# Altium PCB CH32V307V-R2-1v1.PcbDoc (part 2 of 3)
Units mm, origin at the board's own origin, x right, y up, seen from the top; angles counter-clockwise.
Board outline 80 x 115 mm, 2 copper layers (Top Layer, Bottom Layer); 122 components, 134 nets, 559 pads, 721 vias.
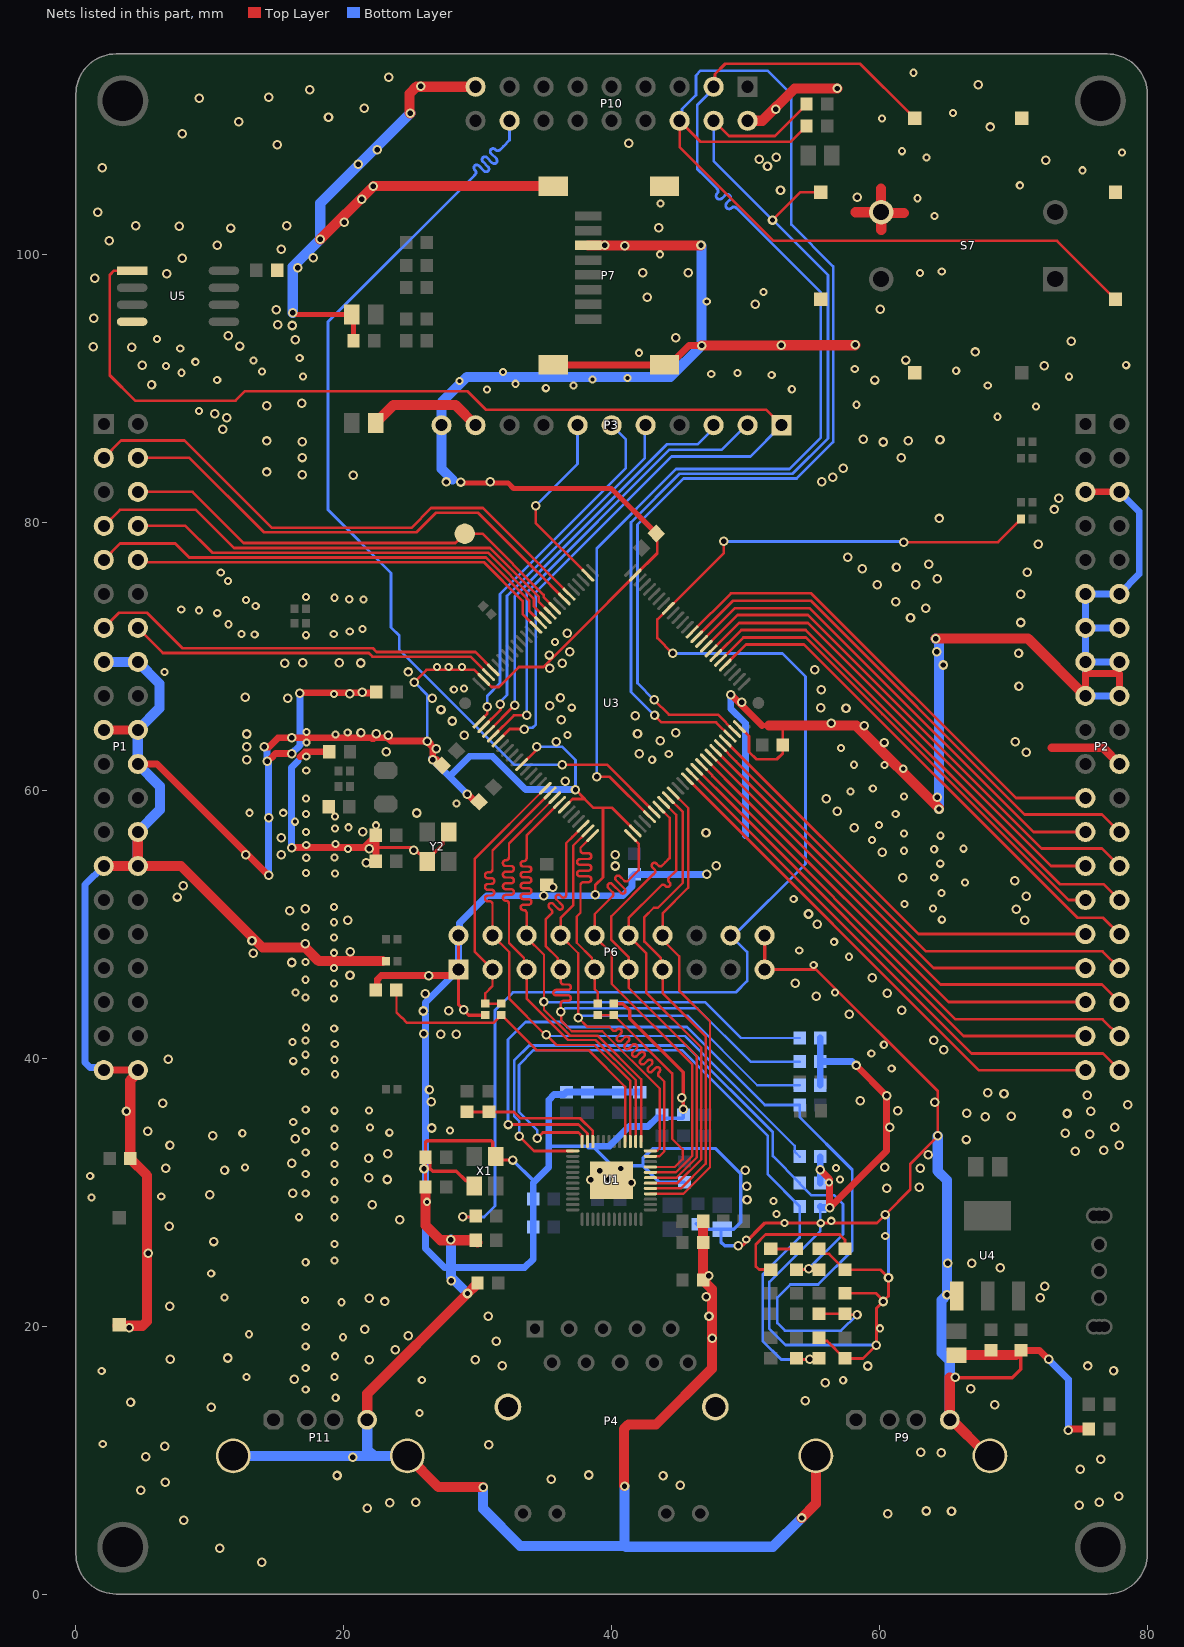
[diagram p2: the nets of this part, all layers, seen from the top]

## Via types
v1: diameter 0.711, hole 0.406, Top Layer to Bottom Layer, tented both sides, 507 vias
v2: diameter 0.61, hole 0.305, Top Layer to Bottom Layer, tented both sides, 214 vias

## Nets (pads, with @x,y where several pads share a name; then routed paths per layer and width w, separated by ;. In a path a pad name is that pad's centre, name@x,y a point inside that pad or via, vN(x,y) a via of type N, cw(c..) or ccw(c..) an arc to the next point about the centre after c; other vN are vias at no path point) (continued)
DVP_PCLK: P10.16 U3.31 | length 75.2
  Top Layer w0.203: v1(36.309,61.928) 39.654,61.928 U3.31@43.182,58.4
  Bottom Layer w0.203: P10.16@32.38,110.007 32.38,108.56 31.917,108.098 31.651,107.831 cw(c31.498,107.984) 31.345,107.831 31.304,107.872 ccw(c31.152,107.72) 30.999,107.567 31.391,107.175 cw(c31.238,107.023) 31.085,106.87 30.694,107.262 ccw(c30.541,107.109) 30.388,106.956 30.78,106.565 cw(c30.627,106.412) 30.475,106.259 30.083,106.651 ccw(c29.93,106.498) 29.778,106.346 29.819,106.305 cw(c29.666,106.152) 29.819,105.999 29.747,105.927 18.818,94.998 18.818,80.963 23.533,76.248 23.533,72.169 24.147,71.555 24.147,70.505 32.724,61.928 v1(36.309,61.928)
DVP_VSYNC: P10.3 S3.1 U3.30 | length 92.6
  Top Layer w0.203: v1(38.89,61.016) 39.859,61.016 U3.30@42.828,58.047 ; P10.3@47.62,112.547 47.721,112.649 47.721,113.501 48.484,114.264 58.545,114.264 62.228,110.581 S3.1@62.626,110.182
  Bottom Layer w0.203: v1(38.89,61.016) 38.89,78.079 44.815,84.005 53.284,84.005 55.622,86.343 55.622,97.192 49.386,103.428 49.314,103.5 ccw(c49.134,103.32) 48.955,103.5 ; P10.3@47.62,112.547 47.62,112.397 46.391,111.168 46.391,106.423 47.004,105.81 47.877,104.937 cw(c47.697,104.757) 47.877,104.578 ; 47.876,104.577 ccw(c48.056,104.397) 47.876,104.218 ccw(c48.056,104.397) 48.235,104.218 48.452,104.435 cw(c48.632,104.255) 48.812,104.435 cw(c48.632,104.255) 48.812,104.075 48.595,103.858 ccw(c48.774,103.679) 48.954,103.499
FSMC_A16: P2.27 U3.58 | length 36.3
  Top Layer w0.203: U3.58@47.425,70.421 49.512,72.509 54.668,72.509 72.816,54.36 P2.27@75.379,54.36
FSMC_A17: P2.28 U3.59 | length 39.6
  Top Layer w0.203: U3.59@47.071,70.775 49.406,73.11 54.666,73.11 72.1,55.676 76.603,55.676 P2.28@77.919,54.36
FSMC_A18: P2.25 U3.60 | length 36.6
  Top Layer w0.203: U3.60@46.718,71.128 49.202,73.613 54.785,73.613 71.497,56.9 P2.25@75.379,56.9
FSMC_CLK: P1.6 tp1.1 U3.84 | length 35.4
  Top Layer w0.203: P1.6@4.621,82.3 8.706,82.3 12.524,78.482 28.34,78.482 tp1.1@29.031,79.174 30.348,79.174 34.924,74.597 34.924,74.436 U3.84@35.757,73.603
FSMC_D0: P2.26 U3.61 | length 39.8
  Top Layer w0.203: U3.61@46.364,71.482 49.051,74.168 54.873,74.168 70.841,58.2 76.619,58.2 P2.26@77.919,56.9
FSMC_D1: P2.23 U3.62 | length 36.9
  Top Layer w0.203: U3.62@46.01,71.835 48.899,74.724 54.909,74.724 70.193,59.44 P2.23@75.379,59.44
FSMC_D2: P1.3 U3.81 | length 41.2
  Top Layer w0.203: P1.3@2.081,84.84 3.37,86.129 8.114,86.129 14.633,79.61 25.046,79.61 26.528,81.092 30.39,81.092 U3.81@36.818,74.664
FSMC_D3: P1.4 U3.82 | length 37.4
  Top Layer w0.203: P1.4@4.621,84.84 8.471,84.84 14.032,79.28 25.432,79.28 26.888,80.736 30.029,80.736 34.412,76.353 34.422,76.353 U3.82@36.464,74.31
FSMC_D4: P2.39 U3.38 | length 38.7
  Top Layer w0.203: U3.38@45.657,60.875 67.412,39.12 P2.39@75.379,39.12
FSMC_D5: P2.40 U3.39 | length 41.1
  Top Layer w0.203: U3.39@46.01,61.229 66.885,40.354 76.685,40.354 P2.40@77.919,39.12
FSMC_D6: P2.37 U3.40 | length 37.3
  Top Layer w0.203: U3.40@46.364,61.582 49.049,58.897 66.286,41.66 P2.37@75.379,41.66
FSMC_D7: P2.38 U3.41 | length 39.6
  Top Layer w0.203: U3.41@46.718,61.936 47.519,61.134 47.519,61.079 65.689,42.909 76.67,42.909 P2.38@77.919,41.66
FSMC_D8: P2.35 U3.42 | length 35.8
  Top Layer w0.203: U3.42@47.071,62.289 49.752,59.608 65.16,44.2 P2.35@75.379,44.2
FSMC_D9: P2.36 U3.43 | length 38.1
  Top Layer w0.203: U3.43@47.425,62.643 64.559,45.509 76.611,45.509 P2.36@77.919,44.2
FSMC_D10: P2.33 U3.44 | length 34.3
  Top Layer w0.203: U3.44@47.778,62.996 64.034,46.74 P2.33@75.379,46.74
FSMC_D11: P2.34 U3.45 | length 36.7
  Top Layer w0.203: U3.45@48.132,63.35 49.303,62.179 63.489,47.993 76.666,47.993 P2.34@77.919,46.74
FSMC_D12: P2.31 U3.46 | length 32.9
  Top Layer w0.203: U3.46@48.485,63.704 62.908,49.28 P2.31@75.379,49.28
FSMC_D13: P2.32 U3.55 | length 39
  Top Layer w0.203: U3.55@48.485,69.36 50.029,70.905 54.365,70.905 74.773,50.496 76.703,50.496 P2.32@77.919,49.28
FSMC_D14: P2.29 U3.56 | length 36.1
  Top Layer w0.203: U3.56@48.132,69.714 49.838,71.42 54.513,71.42 60.215,65.717 74.112,51.82 P2.29@75.379,51.82
FSMC_D15: P2.30 U3.57 | length 39.3
  Top Layer w0.203: U3.57@47.778,70.068 49.688,71.977 54.491,71.977 73.465,53.003 76.737,53.003 P2.30@77.919,51.82
FSMC_NBL0: P1.13 U3.97 | length 31.3
  Top Layer w0.203: P1.13@2.081,72.14 3.21,73.269 5.298,73.269 7.941,70.626 22.167,70.626 22.451,70.342 29.83,70.342 31.161,69.011 U3.97@31.161,69.007
FSMC_NBL1: P1.14 U3.98 | length 27.6
  Top Layer w0.203: P1.14@4.621,72.14 6.495,70.267 21.867,70.267 22.141,69.992 29.469,69.992 U3.98@30.808,68.653
FSMC_NE1_NCE2: P1.10 U3.88 | length 32.4
  Top Layer w0.203: P1.10@4.621,77.22 4.797,77.044 30.466,77.044 33.356,74.154 33.356,73.176 U3.88@34.343,72.189
FSMC_NOE: P1.7 U3.85 | length 37.2
  Top Layer w0.203: P1.7@2.081,79.76 3.279,80.958 8.956,80.958 11.802,78.111 30.907,78.111 34.569,74.45 34.569,74.085 U3.85@35.404,73.25
FSMC_NWAIT: P1.9 U3.87 | length 36
  Top Layer w0.203: P1.9@2.081,77.22 3.307,78.446 7.419,78.446 8.465,77.4 30.613,77.4 33.858,74.155 33.858,73.382 U3.87@34.697,72.542
FSMC_NWE: P1.8 U3.86 | length 33.6
  Top Layer w0.203: P1.8@4.621,79.76 8.173,79.76 10.178,77.755 30.76,77.755 34.213,74.302 34.213,73.733 34.404,73.543 U3.86@35.05,72.896
GND: C1.1 C2.1 C3.1 C4.1 C5.1 C6.1 C7.1 C8.1 C9.1 C10.2 C11.1 C12.1 C13.1 C14.1 C15.1 C16.1 C17.1 C18.2 C19.2 C20.1 C21.1 C22.1 C23.1 C24.1 C25.2 C26.1 C27.1 C28.1 C29.2 C30.1 C31.2 C32.1 C33.2 C34.1 C35.1 C36.1 C37.1 C38.1 C39.2 C40.2 C41.2 P1.15 P1.16 P1.19 P1.20 P1.22 P1.26 P1.27 P1.28 P1.39 P1.40 P2.5 P2.6 P2.11 P2.12 P2.13 P2.14 P2.15 P2.16 P2.17 P2.18 P2.22 P3.11 P4.0 P6.1 P6.2 P6.19 P6.20 P7.6 P7.10 P9.0 P9.4 P10.2 P10.17 P11.0 P11.4 pad.2 R2.2 R4.2 R7.2 R9.2 R15.2 R22.2 R23.2 R26.2 R38.2 R43.2 R47.2 R54.1 R58.1 S1.1 S3.2 S4.2 S5.2 S6.2 S7.3 U1.0 U3.10 U3.19 U3.27 U3.49 U3.74 U3.99 U4.1 U5.4 X1.2 X1.4 Y2.2 Y2.4 | length 909.4
  Top Layer w0.203: v1(25.277,68.097) 26.187,69.007 29.747,69.007 U3.99@30.454,68.3 30.461,68.3 31.028,67.733 31.583,67.733 33.071,69.22 34.909,69.22 37.663,71.973 U3.74@41.768,76.078 43.406,77.717 43.406,78.604 43.351,78.66 43.351,79.062 C26.1@43.406,79.118 ; U3.10@33.282,61.936 33.289,61.936 34.427,63.073 v1(34.427,63.273) ; U3.19@36.464,58.754 37.082,59.372 37.985,59.372 ; v1(37.302,60.068) 37.985,59.385 37.985,59.372 ; v1(38.771,52.202) 38.771,52.922 39.35,53.501 39.35,58.705 ; U3.27@41.768,56.986 40.049,58.705 39.35,58.705 ; U3.49@49.546,64.764 50.253,64.057 50.253,62.884 50.804,62.333 52.334,62.333 52.784,62.783 C37.1@52.784,63.403 52.784,64.634 ; 51.225,64.845 51.743,64.845 ; P6.19@51.43,46.634 55.267,46.634 64.359,37.542 v1(64.359,34.207) ; C18.2@55.495,25.765 55.859,25.402 56.225,25.402 57.402,24.225 R23.2@57.427,24.225 57.428,24.224 60.058,24.224 v1(60.676,23.606) 60.676,22.243 v1@60.319,21.886 ; C29.2@55.859,18.917 55.884,18.892 56.099,18.892 56.71,18.281 ; 56.286,18.705 57.402,17.589 R47.2@57.427,17.589 58.773,17.589 v1(59.772,18.588) 59.772,21.339 v1@60.319,21.886 ; v2@56.511,27.704 59.809,27.704 v1(60.442,28.337) 62.301,30.196 62.301,32.108 v1@64.379,34.187 ; C25.2@57.427,22.461 59.744,22.461 v1@60.319,21.886 ; v1(60.276,21.844) v1@60.319,21.886 ; 37.985,59.372 38.651,58.705 39.35,58.705
  Top Layer w0.254: 22.397,55.777 22.43,55.743 25.186,55.743 25.654,55.276 25.779,55.276 Y2.2@26.227,54.828 ; C13.1@26.103,30.404 C14.1@26.103,32.525 ; Y2.2@26.227,54.703 Y2.2@26.227,54.828 ; Y2.4@27.672,56.731 27.379,56.438 27.379,55.98 Y2.2@26.227,54.828 ; P6.2@28.57,49.174 P6.1@28.57,46.634 28.57,43.997 29.336,43.231 C32.1@30.564,43.231 ; X1.2@29.649,30.339 29.649,30.439 29.226,30.862 29.126,30.862 28.41,31.578 26.632,31.578 26.441,31.769 26.441,32.251 26.166,32.525 C14.1@26.103,32.525 ; X1.4@31.484,32.383 31.507,32.407 v1(32.627,32.407) ; X1.4@31.599,32.689 31.127,33.162 31.127,33.724 31.015,33.835 26.214,33.835 26.103,33.724 C14.1@26.103,32.614 C14.1@26.103,32.525 ; C34.1@40.165,44.081 40.84,44.081 41.346,43.574 41.346,42.966 45.336,38.976 v1(45.336,36.208) ; 49.83,26.083 51.451,27.704 v2@56.511,27.704 ; P6.19@51.43,46.634 P6.20@51.43,49.174 ; 65.253,16.152 69.917,16.152 70.563,16.798 C40.2@70.563,18.194
  Top Layer w0.381: v1(16.193,95.67) 16.193,95.537 C35.1@20.602,95.537 20.722,95.417 C36.1@20.722,93.583 ; v1@28.737,82.957 32.275,82.957 32.676,82.556 39.983,82.556 43.128,79.41 43.241,79.41 C26.1@43.315,79.485
  Top Layer w0.508: P1.39@2.081,39.12 P1.40@4.621,39.12 ; P1.22@4.621,61.98 6.066,61.98 v1(14.388,53.659) ; v1(14.076,63.256) 14.401,63.256 15.078,63.933 22.058,63.933 22.103,63.889 22.241,63.889 22.285,63.933 23.281,63.933 23.529,63.685 v1(26.237,63.685) ; 14.604,62.442 14.913,62.751 v1(16.101,62.751) ; v1(16.102,55.734) 21.501,55.734 C15.1@22.397,56.63 ; v1(16.723,67.272) 16.751,67.3 21.355,67.3 v1(21.383,67.327) ; 16.733,62.512 17.11,62.889 C11.1@18.928,62.889 C11.1@18.908,62.869 ; v1@21.383,67.272 22.34,67.272 C19.2@22.416,67.348 ; R38.2@22.397,45.098 22.503,45.205 22.503,45.893 22.801,46.191 28.108,46.191 P6.1@28.264,46.347 ; C16.1@22.397,54.719 22.397,55.777 C15.1@22.397,56.63 ; C15.1@22.397,56.655 C15.1@22.397,56.63 ; v1@26.44,63.561 26.385,63.506 26.385,63.467 26.649,63.203 v1(26.649,62.305) 26.936,62.305 27.334,61.907 C30.1@27.334,61.876 ; v1(29.23,59.712) 29.285,59.712 29.84,59.157 C31.2@30.101,59.157 ; P7.10@35.65,91.776 P7.10@43.95,91.776 44.325,91.776 45.775,93.226 v1(46.721,93.226) ; v1(48.895,67.132) 48.938,67.132 51.225,64.845 ; v1(55.584,31.669) 56.276,30.977 v1(56.276,28.828) 60.533,33.085 v1(60.533,37.198) 58.283,39.447 v1(58.283,39.466) ; C40.2@70.563,18.194 71.947,18.194 v1(72.626,17.515) ; v1(74.107,12.216) 74.162,12.216 74.275,12.329 R58.1@75.638,12.329 ; P2.17@75.379,67.06 75.379,68.732 77.919,68.732 P2.18@77.919,67.06 ; P2.5@75.379,82.3 P2.6@77.919,82.3
  Top Layer w0.66: P1.19@2.081,64.52 P1.20@4.621,64.52 ; 72.897,63.192 76.708,63.192 P2.22@77.919,61.98
  Top Layer w0.762: P1.27@2.081,54.36 P1.28@4.621,54.36 ; S1.1@3.124,20.032 4.974,20.032 5.308,20.367 5.308,31.26 C17.1@4.055,32.513 4.055,38.355 4.621,38.921 P1.40@4.621,39.12 ; P1.26@4.621,56.9 P1.28@4.621,54.36 ; v1(18.252,101.161) v1(22.217,105.126) P7.10@35.65,105.126 ; P11.4@21.747,13.012 21.747,14.948 v1(29.24,22.441) 29.902,23.103 29.902,23.128 C10.2@29.986,23.212 ; R54.1@22.902,47.26 18.144,47.26 17.124,48.279 13.934,48.279 7.852,54.36 P1.28@4.621,54.36 ; P11.0@24.747,10.312 27.078,7.982 v1(30.404,7.982) ; v1(24.967,110.572) 24.918,110.621 24.918,112.043 25.423,112.547 P10.17@29.84,112.547 ; C13.1@26.103,30.404 26.103,27.542 27.228,26.416 R2.2@29.849,26.416 29.849,26.391 R2.2@29.986,26.254 ; P7.6@38.25,100.701 v1(39.504,100.701) v1(46.675,100.701) ; v1(40.965,8.059) 40.919,8.105 40.919,12.319 41.254,12.654 43.315,12.654 47.487,16.827 47.487,22.776 46.832,23.43 R15.2@46.832,23.455 C21.1@46.832,26.241 C7.1@46.832,27.833 ; P7.10@43.95,105.126 P7.10@44.325,105.126 ; v1(46.721,93.226) 52.636,93.226 v1(52.655,93.244) 58.166,93.244 v1(58.189,93.267) ; P10.2@50.16,110.007 51.256,110.007 53.666,112.418 v1(56.851,112.418) ; 51.743,64.845 58.27,64.845 64.447,58.668 v1(64.447,58.616) ; v1(54.191,5.679) 55.253,6.741 P9.0@55.253,10.312 ; 58.216,103.173 60.117,103.173 S7.3@60.126,103.183 ; 60.124,104.944 60.124,103.185 S7.3@60.126,103.183 ; 60.129,101.862 S7.3@60.129,103.18 ; 61.836,103.114 60.195,103.114 S7.3@60.129,103.18 ; v1(64.204,71.341) 71.098,71.341 P2.17@75.379,67.06 ; 65.253,16.152 P9.4@65.253,13.012 65.403,13.012 67.883,10.533 P9.0@67.883,10.357 ; C39.2@65.749,17.839 C40.2@70.183,17.839 ; S7.3@60.126,103.183 S7.3@60.129,103.18
  Bottom Layer w0.203: v1(25.277,68.097) 26.237,67.138 v1(26.237,63.685) ; v1(34.427,63.273) 36.305,63.273 37.302,62.275 v1(37.302,60.068) ; R22.2@55.584,28.93 55.584,27.105 51.777,23.297 51.777,19.8 52.989,18.588 v1(59.772,18.588) ; v1(60.442,28.337) 60.676,28.104 v1@60.676,23.708
  Bottom Layer w0.254: v1(32.627,32.407) 34.156,30.878 34.156,30.721 34.152,30.716 ; 35.31,33.443 38.318,33.443 ; 38.583,33.443 40.039,31.987 42.343,31.987 ; C8.1@43.722,35.52 45.306,35.52 45.336,35.55 v1(45.336,36.208) ; C6.1@45.433,30.757 43.573,30.757 42.343,31.987 ; C4.1@46.322,27.653 46.722,27.252 C5.1@48.17,27.252 ; v1(49.467,25.996) 48.446,25.996 48.17,26.272 C5.1@48.17,27.252 ; 42.343,31.987 42.343,32.53 43.078,33.265 47.772,33.265 49.64,31.397 49.64,27.769 49.123,27.252 C5.1@48.17,27.252
  Bottom Layer w0.508: P1.39@2.081,39.12 1.891,39.31 1.061,39.31 0.687,39.685 0.687,52.966 P1.27@2.081,54.36 ; v1(14.076,63.256) 14.279,63.054 v1(14.279,62.169) 14.388,62.06 v1(14.388,53.659) ; v1(16.101,62.751) 16.723,63.373 v1(16.723,67.272) ; v1(16.102,55.734) 16.102,61.714 16.579,62.191 ; v1@26.032,43.535 25.977,43.48 25.977,43.442 26.097,43.322 26.097,42.005 26.027,41.934 26.027,41.896 26.082,41.841 26.027,41.786 26.027,41.747 26.097,41.676 26.097,31.929 26.031,31.862 26.031,31.823 26.086,31.768 26.031,31.713 26.031,31.674 26.097,31.607 26.097,25.802 27.518,24.381 28.004,24.381 33.509,24.381 34.152,25.023 C23.1@34.152,27.397 C1.1@34.152,29.489 34.152,30.716 35.31,31.875 35.31,33.443 35.31,36.891 35.71,37.29 36.441,37.29 C24.1@36.628,37.478 C22.1@38.206,37.478 C28.1@40.521,37.478 C27.1@42.03,37.478 ; v1@26.097,43.535 26.097,44.162 28.074,46.138 P6.1@28.57,46.634 P6.2@28.57,49.174 28.652,49.256 28.652,50.11 30.675,52.133 v1(34.933,52.133) 40.824,52.133 41.527,52.836 41.527,53.542 C38.1@41.718,53.732 v1(47.112,53.732) ; v1@26.544,62.398 27.887,61.055 ; v1(29.23,59.712) 27.887,61.055 ; v1(37.302,60.068) 33.585,60.068 31.103,62.55 29.383,62.55 27.887,61.055 ; 38.318,33.443 38.583,33.443 39.859,33.443 41.315,34.899 42.714,34.899 43.378,35.563 C8.1@43.722,35.563 ; C3.1@38.953,30.987 pad.2@39.782,30.987 40.387,30.987 C2.1@40.387,31.006 ; v1(48.895,67.132) 48.895,66.133 50.006,65.022 50.006,56.626 ; R22.2@55.584,28.93 55.648,28.867 56.237,28.867 v1(56.276,28.828) ; R26.2@55.584,30.681 v1(55.584,31.669) R43.2@55.584,32.656 ; R9.2@55.584,37.992 R7.2@55.584,39.753 ; R4.2@55.584,41.515 R7.2@55.584,39.753 ; 57.941,39.753 R7.2@55.584,39.753 ; v1(72.626,17.515) 74.107,16.034 v1(74.107,12.216) ; P2.18@77.919,67.06 P2.17@75.379,67.06 P2.15@75.379,69.6 ; P2.16@77.919,69.6 P2.15@75.379,69.6 ; P2.14@77.919,72.14 P2.13@75.379,72.14 ; P2.6@77.919,82.3 79.392,80.827 79.392,76.154 P2.12@77.919,74.68 P2.11@75.379,74.68 P2.13@75.379,72.14 ; P2.15@75.379,69.6 P2.13@75.379,72.14
  Bottom Layer w0.762: P1.15@2.081,69.6 P1.16@4.621,69.6 6.234,67.987 6.234,66.134 P1.20@4.621,64.52 P1.22@4.621,61.98 6.274,60.328 6.274,58.553 P1.26@4.621,56.9 P1.28@4.621,54.36 ; P11.0@11.747,10.312 22.23,10.312 ; v1(16.193,95.67) 16.193,99.102 v1(18.252,101.161) 18.252,103.857 v1(24.967,110.572) ; P11.4@21.747,13.012 21.747,10.795 22.23,10.312 ; P11.0@24.747,10.312 22.23,10.312 ; v1(28.004,26.462) 28.004,24.381 28.004,23.677 v1(29.24,22.441) ; 28.109,83.219 27.3,84.029 P3.11@27.3,87.274 27.3,88.977 29.208,90.885 44.381,90.885 v1(46.721,93.226) 46.721,100.655 v1(46.675,100.701) ; v1(30.404,7.982) 30.404,6.356 33.172,3.589 40.907,3.589 40.965,3.647 v1(40.965,8.059) ; 41.083,3.529 52.041,3.529 v1(54.191,5.679) ; v1(64.204,71.341) 64.447,71.099 v1(64.447,58.616) ; v1(64.359,34.207) 64.359,31.577 65.045,30.892 v1(65.045,22.351) 64.642,21.948 64.642,18.024 65.253,17.413 P9.4@65.253,13.012
  other v1: 13.885,2.377 10.725,3.431 8.059,5.507 60.629,5.991 65.38,6.174 63.49,6.201 21.743,6.417 74.918,6.639 23.435,6.832 25.38,6.838 76.426,6.847 77.881,7.315 4.841,7.747 45.128,8.126 6.672,8.357 35.505,8.576 43.839,8.831 19.497,8.85 38.301,8.889 74.997,9.33 76.53,10.07 20.682,10.222 5.204,10.238 64.619,10.558 63.096,10.584 6.646,11.047 30.825,11.158 10.118,13.934 68.602,14.134 4.078,14.318 54.446,14.418 66.825,15.336 55.95,15.768 16.301,16.044 65.674,16.173 77.478,16.686 31.847,17.039 59.141,17.026 75.551,17.029 21.906,17.506 29.812,17.506 7.047,17.544 11.325,17.625 23.855,18.241 31.373,18.891 47.516,19.107 24.811,19.271 21.58,19.755 3.972,19.876 30.787,20.729 47.273,20.754 6.998,21.489 23.046,21.845 21.904,22.072 72.004,22.137 47.057,22.211 72.331,22.995 28.032,23.39 47.246,23.75 69.007,24.367 65.102,24.713 66.891,24.713 5.412,25.455 10.306,26.322 6.972,27.473 24.166,27.962 22.128,29.079 50.11,29.443 10.01,29.8 16.197,29.916 60.545,30.285 62.957,30.38 50.076,30.448 41.454,30.709 23.246,30.953 38.43,30.939 21.867,31.096 39.129,31.612 49.974,31.642 11.097,31.655 25.992,31.768 40.695,31.773 6.703,31.781 63.055,31.793 60.387,31.872 16.129,32.169 21.849,32.541 63.647,32.811 23.279,32.892 74.628,33.06 76.743,33.144 77.916,33.502 7.025,33.509 66.468,33.938 16.394,33.996 10.207,34.219 75.701,34.317 73.871,34.412 5.356,34.568 26.565,34.798 60.783,34.846 77.558,34.871 67.908,35.646 69.832,35.676 74.006,35.881 66.518,35.913 3.777,36.054 75.766,36.044 61.378,36.076 78.535,36.532 6.499,36.639 64.139,36.72 26.533,36.77 58.57,36.826 45.248,37.046 75.521,37.251 69.299,37.363 68.086,37.422 26.401,37.657 6.909,39.935 64.797,40.636 64.05,41.348 28.397,41.799 27.234,41.813 25.988,41.841 57.728,43.281 25.939,43.535 27.848,43.569 61.662,43.578 28.953,43.614 55.291,44.629 26.092,44.814 60.594,44.848 53.721,45.608 59.453,46.027 26.358,46.151 20.467,46.188 16.106,47.156 13.241,47.845 20.492,47.956 17.137,48.55 13.148,48.79 55.347,50.022 20.286,50.305 70.856,50.322 54.702,50.777 15.974,51.017 70.225,51.117 17.137,51.182 7.568,52.045 70.965,52.109 35.607,52.759 8.025,52.879 70.098,53.264 61.735,53.495 40.266,54.362 47.8,54.385 21.675,54.592 12.668,55.204 15.345,55.216 40.275,55.2 60.194,55.374 25.243,55.528 21.89,55.644 15.328,56.48 47.049,56.832 21.405,56.924 58.125,57.21 14.395,57.975 25.458,58.319 56.859,58.456 56.035,59.384 64.326,59.491 36.541,60.699 12.773,62.286 42.057,62.73 70.96,62.865 23.164,62.904 26.894,63.13 12.773,63.252 60.35,63.581 35.869,63.641 70.129,63.639 43.626,63.718 16.128,63.923 29.007,64.124 23.329,64.135 12.773,64.217 22.413,64.226 41.933,64.25 21.286,64.301 44.8,64.299 58.88,64.818 56.406,65.028 28.109,65.188 36.229,65.286 41.781,65.586 27.262,66.046 57.503,66.148 55.613,66.171 35.37,66.324 49.727,66.602 15.83,66.895 26.609,66.902 12.643,66.952 36.183,66.93 20.463,67.226 55.66,67.525 70.418,67.8 24.804,68.849 55.168,69.006 35.383,69.124 64.778,69.371 15.605,69.512 21.263,69.519 36.323,69.517 16.945,69.533 19.679,69.546 35.336,70.116 70.384,70.24 36.884,70.351 64.266,70.351 36.688,71.74 70.556,72.543 62.319,72.882 63.441,73.605 61.222,74.079 70.556,74.639 59.826,75.35 62.718,75.375 64.313,75.824 71.037,76.289 58.705,76.546 61.272,76.671 63.665,76.895 57.633,77.419 71.854,78.397 64.463,80.31 73.037,80.983 73.386,81.806 27.641,83.037 28.737,83.033 30.949,83.056 55.682,83.04 56.511,83.392 16.902,83.56 20.721,83.541 14.261,83.782 57.29,84.07 61.621,84.847 16.902,84.862 60.283,86.021 16.902,86.032 14.247,86.097 62.152,86.117 64.521,86.194 58.786,86.224 10.948,86.965 11.247,87.845 10.381,88.133 14.247,88.737 16.872,88.906 5.647,90.302 59.664,90.65 4.939,91.736 72.318,91.731 61.973,92.143 67.148,92.743 4.181,93.096 1.281,93.134 12.232,93.188 74.332,93.543 16.395,93.67 44.795,93.791 11.373,93.956 16.149,94.721 15.076,94.765 1.324,95.259 14.971,95.912 60.071,95.921 50.724,96.305 42.661,96.817 1.423,98.239 6.797,98.578 42.342,98.645 45.722,98.645 16.578,99.02 7.929,99.735 17.726,99.788 15.328,100.42 40.992,100.678 10.538,100.719 2.491,101.039 11.547,101.999 43.51,102.018 7.732,102.122 4.459,102.171 15.754,102.164 20.028,102.42 1.619,103.185 21.331,104.146 58.333,104.306 52.611,104.822 1.979,106.494 51.641,106.6 21.066,106.771 72.406,107.056 51.022,107.138 52.298,107.298 22.512,107.859 15.046,108.231 41.266,108.321 7.93,109.04 68.259,109.544 12.164,109.923 18.861,110.275 52.245,110.857 21.546,110.946 9.194,111.702 14.397,111.765 17.468,112.323 25.733,112.587 67.37,112.684 23.369,113.273
  other v2: 2.006,11.207 25.666,13.526 19.396,14.658 17.159,15.281 25.829,15.972 57.293,15.96 19.304,16.196 12.732,16.215 1.924,16.647 17.159,16.888 19.346,17.749 17.159,18.495 19.936,19.171 12.933,19.396 60.04,19.841 17.161,19.951 19.82,21.785 17.109,21.95 11.087,22.132 10.101,23.923 17.159,24.771 19.304,24.916 19.304,26.141 50.054,26.481 60.433,26.73 55.616,27.69 52.907,27.713 56.4,27.869 16.651,28.138 19.304,28.134 52.323,28.364 26.218,29.288 52.092,29.342 19.304,29.46 1.169,29.614 6.372,29.682 17.159,29.897 56.229,30.726 19.304,30.786 57.042,30.956 1.067,31.213 17.159,31.352 56.763,31.81 12.63,31.859 19.304,32.113 17.159,32.959 19.304,33.439 12.426,34.409 23.402,34.448 17.159,34.566 27.931,34.603 19.304,34.766 21.97,34.835 16.231,35.234 19.304,36.092 21.892,36.113 17.159,36.173 19.342,38.809 17.124,39.018 60.915,39.249 16.23,39.787 19.3,39.897 17.152,40.274 59.393,40.371 60.327,41.014 19.328,41.069 16.182,41.225 17.152,41.334 19.286,42.227 17.18,42.282 19.269,44.459 17.137,44.549 16.395,44.922 56.687,44.908 19.269,45.599 17.137,45.866 19.269,46.739 55.089,46.963 17.137,47.182 57.716,47.586 19.269,47.879 54.012,48.059 56.62,48.701 19.269,49.019 17.137,49.815 19.269,50.159 64.657,50.354 63.998,51.195 19.269,51.299 61.868,51.528 53.596,51.895 64.627,52.356 66.394,53.126 64.087,53.503 19.335,53.792 17.189,53.839 64.539,54.535 17.201,54.976 19.316,54.988 61.824,55.5 20.309,55.62 64.087,55.611 66.283,55.655 17.201,55.936 19.373,56.014 59.446,56.301 64.568,56.625 61.841,56.788 17.176,56.909 19.354,57.172 20.359,57.25 22.397,57.399 59.975,57.42 16.349,57.67 19.354,58.065 17.189,58.235 61.212,58.244 12.958,58.332 15.482,58.332 28.41,59.027 17.189,59.397 61.824,59.56 57.826,59.923 59.504,60.158 17.201,61.494 61.779,61.623 60.388,61.895 58.091,61.925 43.03,62.297 17.201,62.542 44.264,62.721 57.12,63.161 17.214,63.578 36.7,64.135 19.378,64.18 20.295,64.331 17.214,64.374 37.024,66.183 19.282,67.211 28.217,67.552 28.974,67.606 6.622,68.843 26.957,69.214 27.836,69.224 28.832,69.23 35.781,71.077 17.188,71.595 13.349,71.642 12.372,71.679 19.254,71.686 20.449,71.862 21.394,72.047 11.396,72.412 10.551,73.238 9.199,73.454 7.864,73.526 13.424,73.782 12.692,74.223 21.468,74.252 20.412,74.28 19.319,74.391 17.188,74.446 11.349,75.65 10.814,76.289 68.816,87.908 9.189,88.334 71.679,88.671 58.282,88.801 30.693,89.934 53.457,89.958 35.088,90.04 37.161,90.243 68.085,90.23 32.813,90.365 28.651,90.58 10.55,90.648 38.583,90.69 41.184,90.812 74.161,90.898 16.946,90.92 51.954,91.015 47.443,91.096 49.394,91.178 7.896,91.193 31.892,91.251 13.884,91.295 65.731,91.344 58.153,91.471 6.739,91.703 78.423,91.757 8.916,92.009 13.272,92.111 16.708,92.281 42.038,92.681 7.793,92.996 6.058,93.711 47.106,96.505 51.352,97.221 63.018,98.632 64.655,98.758 43.619,100.037 64.116,102.898 43.663,103.837 62.843,104.222 70.482,105.189 75.167,106.31 63.505,107.277 78.12,107.634 61.672,107.735 60.195,110.18 65.491,110.587 62.538,113.592
GPHY_RGMII_MCO: P6.18 R14.2 R48.2 U3.67 | length 108.2
  Top Layer w0.203: v1(28.886,28.16) 29.79,28.16 R14.2@29.849,28.219 ; v1(44.562,70.234) 43.415,71.381 43.415,72.775 U3.67@44.243,73.603 48.38,77.741 v1(48.38,78.599) ; v1(61.799,78.545) 68.846,78.545 70.343,80.041 70.368,80.041 70.566,80.24 R48.2@70.566,80.265
  Bottom Layer w0.203: v1(28.886,28.16) 30.481,28.16 31.289,28.968 31.289,43.59 32.628,44.929 49.271,44.929 50.125,45.782 50.125,47.94 P6.18@48.89,49.174 49.123,49.174 54.475,54.527 54.475,68.518 52.759,70.234 v1(44.562,70.234) ; v1(48.38,78.599) 61.745,78.599 v1(61.799,78.545)
GPHY_RGMII_RXC: R38.1 R49.1 U1.28 | length 25.7
  Top Layer w0.178: R38.1@23.937,45.098 23.937,43.441 23.937,43.416 24.313,43.04 24.338,43.04 24.729,42.648 31.187,42.648 31.522,42.983 31.522,43.02 31.733,43.231 31.783,43.231 31.994,43.02 31.994,43.01 34.387,40.616 38.269,40.616 41.018,37.867 41.018,33.804 U1.28@41,33.786
GPHY_RGMII_RXC_P: C32.2 P6.3 R49.2 U3.15 | length 20.3
  Top Layer w0.178: R49.2@31.758,44.081 C32.2@30.564,44.081 30.564,44.853 31.11,45.399 P6.3@31.11,46.634 29.769,47.976 29.769,54.886 U3.15@35.05,60.168
GPHY_RGMII_RXD0: P6.5 U1.26 U3.17 | length 36.8
  Top Layer w0.178: P6.5@33.365,46.349 P6.5@33.5,46.214 ; U3.17@35.757,59.461 32.335,56.039 32.335,55.363 32.335,55.01 cw(c32.119,55.01) 32.119,54.794 32.097,54.794 ccw(c32.097,54.578) 32.097,54.362 32.497,54.362 cw(c32.497,54.146) 32.497,53.93 32.097,53.93 ccw(c32.097,53.714) 32.097,53.498 32.497,53.498 cw(c32.497,53.283) 32.497,53.067 32.097,53.067 ccw(c32.097,52.851) 32.097,52.635 32.497,52.635 cw(c32.497,52.419) 32.497,52.203 32.097,52.203 ccw(c32.097,51.987) 32.097,51.771 32.119,51.771 cw(c32.119,51.555) 32.335,51.555 32.335,51.466 32.335,48.612 33.463,47.484 33.463,46.821 P6.5@33.65,46.634 33.65,44.464 36.747,41.367 38.803,41.367 41.8,38.37 U1.26@41.8,33.786
GPHY_RGMII_RXD1: P6.6 R4.1 U1.25 U3.18 | length 56.8
  Top Layer w0.178: U3.18@36.111,59.107 34.948,57.944 33.65,56.646 33.65,55.258 33.65,54.932 cw(c33.447,54.932) 33.447,54.729 33.415,54.729 ccw(c33.415,54.526) 33.415,54.323 33.808,54.323 cw(c33.808,54.119) 33.808,53.916 33.415,53.916 ccw(c33.415,53.713) 33.415,53.51 33.808,53.51 cw(c33.808,53.307) 33.808,53.103 33.415,53.103 ccw(c33.415,52.9) 33.415,52.697 33.808,52.697 cw(c33.808,52.494) 33.808,52.291 33.415,52.291 ccw(c33.415,52.087) 33.415,51.884 33.808,51.884 cw(c33.808,51.681) 33.808,51.478 33.415,51.478 ccw(c33.415,51.275) 33.415,51.071 33.447,51.071 cw(c33.447,50.868) 33.65,50.868 33.65,50.779 P6.6@33.65,49.174 33.65,49.034 34.95,47.733 v1(34.95,44.221) 34.95,43.631 36.884,41.698 38.94,41.698 42.2,38.437 U1.25@42.2,33.786
  Bottom Layer w0.178: v1(34.95,44.221) 34.995,44.177 46.999,44.177 49.661,41.515 R4.1@54.044,41.515
GPHY_RGMII_RXD2: P6.7 R7.1 U1.24 U3.23 | length 56.3
  Top Layer w0.178: U3.23@37.879,57.34 37.07,56.531 36.608,56.069 36.608,52.472 36.608,52.204 cw(c36.405,52.204) 36.262,52.06 36.159,52.163 ccw(c36.015,52.019) 35.871,52.163 ccw(c36.015,52.019) 35.871,51.876 36.297,51.45 cw(c36.154,51.306) 36.297,51.162 cw(c36.154,51.306) 36.01,51.162 35.635,51.538 ccw(c35.491,51.394) 35.347,51.538 ccw(c35.491,51.394) 35.347,51.25 35.511,51.087 cw(c35.367,50.943) 35.511,50.799 35.448,50.736 35.074,50.362 35.074,48.389 35.986,47.476 35.986,46.838 P6.7@36.19,46.634 36.209,46.615 36.209,45.806 36.209,45.717 ccw(c36.412,45.717) 36.412,45.514 36.756,45.514 cw(c36.756,45.311) 36.756,45.108 35.844,45.108 ccw(c35.844,44.905) 35.844,44.701 36.756,44.701 cw(c36.756,44.498) 36.756,44.295 36.412,44.295 ccw(c36.412,44.092) 36.209,44.092 36.209,43.479 36.209,43.477 36.228,43.458 36.228,42.82 37.02,42.028 39.303,42.028 43.594,37.737 43.594,33.274 43.415,33.094 42.908,33.094 U1.24@42.9,33.086
  Bottom Layer w0.178: v1(36.195,43.485) 36.293,43.485 36.54,43.731 46.392,43.731 50.37,39.753 R7.1@54.044,39.753
GPHY_RGMII_RXD3: P6.8 R9.1 U1.23 U3.24 | length 55.3
  Top Layer w0.178: U3.24@38.232,56.986 37.122,55.876 37.122,51.417 36.19,50.485 P6.8@36.19,49.174 37.516,47.849 v1(37.516,43.028) 38.174,42.37 39.818,42.37 40.016,42.171 40.079,42.108 ccw(c40.223,42.252) 40.366,42.108 40.406,42.148 cw(c40.55,42.005) 40.694,42.148 cw(c40.55,42.005) 40.694,41.861 40.441,41.608 ccw(c40.585,41.465) 40.441,41.321 ccw(c40.585,41.465) 40.728,41.321 40.981,41.574 cw(c41.125,41.43) 41.268,41.574 cw(c41.125,41.43) 41.268,41.286 41.016,41.034 ccw(c41.159,40.89) 41.016,40.746 ccw(c41.159,40.89) 41.303,40.746 41.556,40.999 cw(c41.699,40.855) 41.843,40.712 41.59,40.459 ccw(c41.734,40.315) 41.59,40.171 ccw(c41.734,40.315) 41.878,40.171 42.131,40.424 cw(c42.274,40.281) 42.418,40.424 cw(c42.274,40.281) 42.418,40.137 42.165,39.884 ccw(c42.309,39.74) 42.165,39.597 ccw(c42.309,39.74) 42.452,39.597 42.705,39.85 cw(c42.849,39.706) 42.993,39.85 cw(c42.849,39.706) 42.993,39.562 42.74,39.309 ccw(c42.883,39.166) 42.74,39.022 ccw(c42.883,39.166) 43.027,39.022 43.28,39.275 cw(c43.424,39.131) 43.567,39.275 cw(c43.424,39.131) 43.567,38.987 43.527,38.947 ccw(c43.671,38.804) 43.527,38.66 43.926,38.261 43.926,37.749 43.926,33.048 43.565,32.686 U1.23@42.9,32.686
  Bottom Layer w0.178: v1(37.516,43.028) 37.66,43.028 37.807,43.174 45.692,43.174 50.875,37.992 R9.1@54.044,37.992
GPHY_RGMII_RXDV: P6.4 R43.1 U1.27 U3.16 | length 59.5
  Top Layer w0.178: v1@35.128,41.716 35.166,41.716 35.887,40.995 38.708,40.995 41.4,38.303 U1.27@41.4,33.786 ; v1(35.128,41.754) 35.052,41.754 32.367,44.438 32.367,47.917 P6.4@31.11,49.174 31.11,51.42 31.11,51.509 ccw(c30.894,51.509) 30.894,51.725 30.758,51.725 cw(c30.758,51.94) 30.758,52.156 31.021,52.156 ccw(c31.021,52.372) 31.021,52.588 30.758,52.588 cw(c30.758,52.804) 30.758,53.02 31.021,53.02 ccw(c31.021,53.236) 31.021,53.452 30.758,53.452 cw(c30.758,53.668) 30.758,53.884 30.894,53.884 ccw(c30.894,54.099) 31.11,54.099 31.11,54.435 31.11,55.521 U3.16@35.404,59.814
  Bottom Layer w0.178: v1(35.128,41.754) 35.206,41.676 35.206,41.668 45.479,41.668 53.668,33.479 53.668,33.032 R43.1@54.044,32.656
GPHY_RGMII_TXC: C34.2 R50.1 U1.21 | length 16.7
  Top Layer w0.178: R50.1@38.971,43.231 40.19,43.231 40.401,43.02 40.401,42.995 44.516,38.88 44.516,33.991 45.299,33.208 45.299,32.468 44.717,31.886 U1.21@42.9,31.886
GPHY_RGMII_TXC_P: P6.9 R50.2 U3.25 | length 18.5
  Top Layer w0.178: U3.25@38.586,56.633 38.518,56.565 37.675,55.722 37.675,55.529 ccw(c37.891,55.529) 37.891,55.313 38.272,55.313 cw(c38.272,55.097) 38.272,54.882 37.643,54.882 ccw(c37.643,54.666) 37.643,54.45 38.272,54.45 cw(c38.272,54.234) 38.272,54.018 37.643,54.018 ccw(c37.643,53.802) 37.643,53.586 38.272,53.586 cw(c38.272,53.37) 38.272,53.154 37.891,53.154 ccw(c37.891,52.938) 37.675,52.938 37.675,52.429 37.675,52.418 37.675,50.874 37.396,50.595 37.396,48.627 38.539,47.484 38.539,46.825 P6.9@38.73,46.634 38.73,45.185 38.971,44.944 R50.2@38.971,44.081
GPHY_RGMII_TXD0: P6.11 U1.19 U3.32 | length 35.8
  Top Layer w0.178: P6.11@41.095,46.452 41.27,46.277 41.27,45.265 46.359,40.176 46.359,32.594 44.851,31.086 U1.19@42.9,31.086 ; P6.11@41.27,46.634 41.27,47.555 39.987,48.837 39.987,50.608 43.138,53.758 43.201,53.821 ccw(c43.057,53.965) 43.201,54.109 43.054,54.256 cw(c43.197,54.4) 43.054,54.543 cw(c43.197,54.4) 43.341,54.543 43.488,54.396 ccw(c43.632,54.54) 43.776,54.396 44.012,54.632 44.016,54.637 44.331,54.951 44.331,57.959 U3.32@43.536,58.754
GPHY_RGMII_TXD1: P6.12 U1.18 U3.33 | length 35.9
  Top Layer w0.178: U1.18@42.9,30.686 44.918,30.686 46.689,32.457 46.689,40.802 42.578,44.912 42.578,47.866 P6.12@41.27,49.174 41.27,50.472 43.351,52.553 43.702,52.904 cw(c43.845,52.76) 43.989,52.904 44.036,52.857 ccw(c44.18,53) 44.323,52.857 ccw(c44.18,53) 44.323,53.144 44.276,53.191 cw(c44.42,53.335) 44.276,53.478 44.798,54 44.813,54.015 44.813,58.183 U3.33@43.889,59.107
GPHY_RGMII_TXD2: P6.13 U1.17 U3.34 | length 35.9
  Top Layer w0.178: U1.17@42.9,30.286 45.173,30.286 47.019,32.133 47.019,41.669 43.81,44.879 P6.13@43.81,46.634 43.679,46.765 43.679,47.484 42.451,48.712 42.451,50.557 43.143,51.25 43.466,51.25 45.321,53.105 45.321,58.382 U3.34@44.243,59.461
GPHY_RGMII_TXD3: P6.14 U1.16 U3.35 | length 35.9
  Top Layer w0.178: U1.16@42.9,29.886 45.363,29.886 47.349,31.872 47.349,42.767 45.042,45.074 45.042,47.62 43.81,48.852 43.81,50.827 45.728,52.744 45.728,58.683 U3.35@44.596,59.814
GPHY_RGMII_TXEN: P6.10 U1.20 U3.26 | length 35.9
  Top Layer w0.178: U3.26@41.414,56.633 42.016,56.03 42.016,54.137 42.016,54.048 41.228,53.26 cw(c41.085,53.404) 40.941,53.26 40.618,53.583 ccw(c40.474,53.439) 40.331,53.583 ccw(c40.474,53.439) 40.331,53.296 40.98,52.647 cw(c40.836,52.503) 40.98,52.359 cw(c40.836,52.503) 40.692,52.359 40.041,53.011 ccw(c39.897,52.867) 39.753,53.011 ccw(c39.897,52.867) 39.753,52.724 40.079,52.398 cw(c39.935,52.254) 40.079,52.111 40.016,52.048 38.73,50.762 38.73,49.101 40.013,47.818 40.013,45.553 46.028,39.537 46.028,32.73 44.784,31.486 U1.20@42.9,31.486
I2C2_SCL: P10.4 R51.1 S5.1 U3.47 | length 78.9
  Top Layer w0.203: v1(43.205,65.605) 43.717,65.092 47.804,65.092 U3.47@48.839,64.057 ; P10.4@47.62,110.007 48.764,108.864 52.188,108.864 54.552,111.227 R51.1@54.552,111.252 ; v1(52.015,102.596) 54.092,104.674 S5.1@55.627,104.674
  Bottom Layer w0.203: v1(43.205,65.605) 41.444,67.366 41.444,80.021 45.072,83.649 53.504,83.649 56.153,86.298 56.153,98.483 47.62,107.016 P10.4@47.62,110.007
I2C2_SDA: P10.6 R52.1 S6.1 U3.48 | length 126.7
  Top Layer w0.203: v1(43.176,66.773) 44.287,65.662 47.941,65.662 U3.48@49.192,64.411 ; R52.1@54.552,109.615 53.368,108.431 46.657,108.431 P10.6@45.08,110.007 45.08,108.033 52.073,101.04 73.259,101.04 S6.1@77.626,96.674
  Bottom Layer w0.203: v1(43.176,66.773) 41.933,68.016 41.933,79.848 45.378,83.294 53.816,83.294 56.547,86.025 56.547,99.142 53.422,102.267 53.422,111.955 51.632,113.745 46.652,113.745 46.3,113.392 46.3,111.92 45.252,110.871 45.252,110.179 P10.6@45.08,110.007
INTB: R16.1 R17.1 U1.34 | length 10.7
  Top Layer w0.203: R17.1@29.293,35.971 29.322,36 R16.1@30.856,36 32.715,36 33.198,35.517 37.657,35.517 38.6,34.574 U1.34@38.6,33.786
LCD_BLK: P3.5 U3.2 | length 27.5
  Top Layer w0.203: U3.2@30.454,64.764 31.699,66.009 v1(31.699,66.446)
  Bottom Layer w0.203: v1(31.699,66.446) 31.699,66.647 32.188,67.136 32.188,74.533 42.481,84.826 42.481,87.215 P3.5@42.54,87.274
LCD_CS1: P3.3 U3.3 | length 31.2
  Top Layer w0.203: U3.3@30.808,64.411 v1(32.766,66.369)
  Bottom Layer w0.203: v1(32.766,66.369) 32.766,74.473 44.155,85.862 46.44,85.862 47.62,87.042 P3.3@47.62,87.274
LCD_CS2: P3.2 U3.4 | length 34.1
  Top Layer w0.203: U3.4@31.161,64.057 32.712,65.608 v1(33.655,65.608)
  Bottom Layer w0.203: v1(33.655,65.608) 33.655,74.767 44.334,85.446 48.231,85.446 50.16,87.375 P3.2@50.16,87.274
LCD_DC: P3.6 U3.1 | length 27.1
  Top Layer w0.203: U3.1@30.101,65.118 30.718,65.735 v1(30.718,66.263)
  Bottom Layer w0.203: v1(30.718,66.263) 30.718,67.074 31.659,68.016 31.659,74.667 41.065,84.073 41.065,86.209 P3.6@40,87.274
LCD_INT: P3.1 U3.5 U5.1 | length 98.3
  Top Layer w0.203: U5.1@4.196,98.811 2.843,98.811 2.529,98.498 2.529,91.003 4.427,89.106 11.92,89.106 12.628,89.814 29.222,89.814 30.602,88.434 51.54,88.434 P3.1@52.7,87.274 ; U3.5@31.515,63.704 32.397,64.586 v1(33.48,64.586)
  Bottom Layer w0.203: v1(33.48,64.586) 33.577,64.683 34.085,64.683 34.342,64.941 34.342,74.806 44.476,84.939 50.365,84.939 P3.1@52.7,87.274
LCD_RST: P3.7 U3.77 | length 14.1
  Top Layer w0.203: v1(34.331,81.257) 34.331,79.986 38.232,76.085 U3.77@38.232,76.078
  Bottom Layer w0.203: v1(34.331,81.257) 37.46,84.386 P3.7@37.46,87.274
LCD_VCC: F2.1 P3.10 | length 8.7
  Top Layer w0.762: F2.1@22.382,87.434 22.382,87.589 22.581,87.788 22.736,87.788 23.737,88.79 28.325,88.79 P3.10@29.84,87.274
LED0/PHYAD0: C25.1 R30.2 R33.2 U1.35 | length 69
  Top Layer w0.203: v1(32.267,35.058) 37.525,35.058 38.197,34.387 38.197,33.79 U1.35@38.2,33.786 ; R30.2@55.495,20.921 C25.1@57.427,20.921 57.498,20.85 v1(58.325,20.85)
  Bottom Layer w0.203: v1(32.267,35.058) 32.267,41.414 33.572,42.719 36.316,42.719 36.693,42.341 45.618,42.341 51.446,36.513 R33.2@54.044,36.513 54.044,35.606 57.967,31.683 57.967,25.652 55.427,23.112 53.345,23.112 52.376,22.143 52.376,20.228 52.939,19.665 57.14,19.665 v1(58.325,20.85)
LED1/CFG_LDO0: C29.1 R22.1 R40.2 U1.36 | length 55.1
  Top Layer w0.203: v1(34.456,34.047) 34.863,34.454 37.527,34.454 37.8,34.181 U1.36@37.8,33.786 ; R40.2@53.817,17.589 53.891,17.515 v1(54.798,17.515) 54.871,17.589 54.945,17.515 55.421,17.515 C29.1@55.495,17.589
  Bottom Layer w0.203: v1(34.456,34.047) 34.456,34.62 33.078,35.998 33.078,39.507 34.181,40.61 45.264,40.61 51.664,34.21 51.664,31.336 54.044,28.955 R22.1@54.044,28.93 54.044,26.619 51.277,23.851 51.277,18.908 52.669,17.515 v1(54.798,17.515)
LED2/CFG_LDO1: C18.1 R19.2 R26.1 U1.37 | length 48.8
  Top Layer w0.203: v1(33.112,34.175) 34.2,33.086 U1.37@37.1,33.086 ; R19.2@53.817,24.225 C18.1@55.495,24.225
  Bottom Layer w0.203: v1(33.112,34.175) 33.112,35.297 32.722,35.687 32.722,39.839 33.849,40.966 45.558,40.966 52.042,34.481 52.042,32.709 54.044,30.706 R26.1@54.044,30.681 54.044,30.656 54.929,29.772 56.635,29.772 57.283,29.123 57.283,26.856 v1(54.716,24.289)
LED_blue_n: D1.K R23.1 | length 10.7
  Top Layer w0.203: D1.K@51.886,24.225 51.012,24.225 50.773,24.465 50.773,26.117 51.497,26.841 57.03,26.841 57.427,26.444 R23.1@57.427,25.765
LED_blue_p: D1.A R19.1 | length 1.9
  Top Layer w0.203: D1.A@51.886,25.765 R19.1@53.817,25.765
